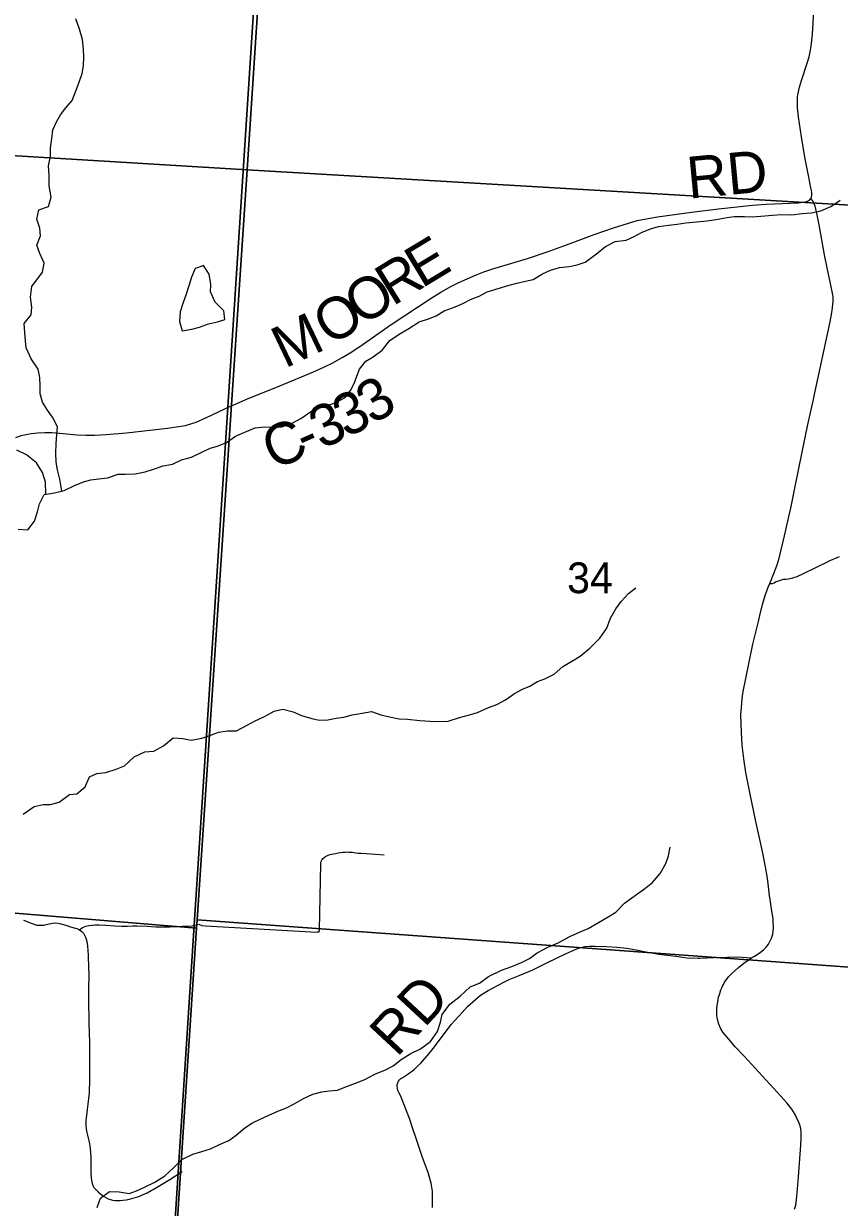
# Model space of a CAD drawing. Extents: x 0 to 34, y 0 to 22.
# Drawn here: x 3.074 to 4.184, y 15.5 to 17.112 of the extents above; entities that cross this region are included whole.
import ezdxf

# ---------------------------------------------------------------- set-up
doc = ezdxf.new("R2010")
doc.units = 0
for name, color, linetype in [('GM_X_Corporation', 7, 'Continuous'), ('GM_X_County_Road', 7, 'Continuous'), ('GM_X_County_Road_Text', 7, 'Continuous'), ('GM_X_Major_River', 7, 'Continuous'), ('GM_X_Minor_Lake', 7, 'Continuous'), ('GM_X_Minor_River', 7, 'Continuous'), ('GM_X_Section_Text', 7, 'Continuous'), ('GM_X_Township_Road', 7, 'Continuous'), ('GM_X_Township_Road_Text', 7, 'Continuous'), ('GM_X_Township_Text', 7, 'Continuous')]:
    doc.layers.add(name, color=color, linetype=linetype)

msp = doc.modelspace()

# ---------------------------------------------------------------- linework, layer by layer
at = {"layer": 'GM_X_Corporation'}
for points in [[(2.1, 19.0816), (2.1, 14.1), (3.1902, 14.1), (3.1919, 14.1255), (3.2339, 14.7735), (3.2844, 15.554), (3.3059, 15.8844), (3.3516, 16.5898), (3.3951, 17.2616), (3.507, 18.9883), (2.9513, 19.0267), (2.509, 19.0572), (2.4972, 19.0545), (2.4649, 19.0567)], [(2.436, 18.0137), (3.4457, 17.9455), (3.3779, 16.9127), (2.3682, 16.9741)], [(3.4457, 17.9455), (4.4596, 17.8697), (4.3853, 16.8539), (3.3779, 16.9127)], [(3.3779, 16.9127), (3.31, 15.8916), (3.3089, 15.8803), (2.2939, 15.964), (2.3682, 16.9741)], [(4.3853, 16.8539), (4.3528, 16.4147), (4.3239, 16.0112), (4.31, 15.819), (3.31, 15.8916), (3.3779, 16.9127)], [(2.2939, 15.964), (3.3089, 15.8803), (3.2437, 14.8797), (2.2272, 14.9411)], [(3.3089, 15.8803), (3.31, 15.8916), (4.31, 15.819), (4.245, 14.8084), (3.2437, 14.8797)]]:
    msp.add_lwpolyline(points, close=True, dxfattribs=at)
at = {"layer": 'GM_X_County_Road'}
for points in [[(3.363, 16.5943), (3.3763, 16.6), (3.4224, 16.6185), (3.4683, 16.6376), (3.4824, 16.644), (3.4935, 16.6496), (3.507, 16.6571), (3.5202, 16.6651), (3.5358, 16.6753), (3.5739, 16.7021), (3.6282, 16.7381), (3.6414, 16.7462), (3.655, 16.7538), (3.6661, 16.7594), (3.6887, 16.7695), (3.7002, 16.7741), (3.7121, 16.778), (3.7596, 16.7922), (3.7891, 16.8021), (3.8212, 16.8137), (3.8502, 16.8246), (3.8765, 16.8338), (3.897, 16.8404), (3.909, 16.8437), (3.9212, 16.8463), (3.9366, 16.8488), (3.9827, 16.8551), (4.0197, 16.8597), (4.066, 16.8646), (4.0846, 16.866), (4.1279, 16.8681), (4.137, 16.8692), (4.1407, 16.8702), (4.1432, 16.8715), (4.1453, 16.8737), (4.1462, 16.8758), (4.1467, 16.8788), (4.1465, 16.8818), (4.1461, 16.8848), (4.1454, 16.8883), (4.1424, 16.9029), (4.1371, 16.9303), (4.1325, 16.9577), (4.1284, 16.985), (4.1272, 16.9974), (4.1269, 17.0064), (4.1272, 17.0122), (4.1275, 17.015), (4.1298, 17.0255), (4.1324, 17.0344), (4.1404, 17.058), (4.1429, 17.0669), (4.1449, 17.0759), (4.1463, 17.0851), (4.1474, 17.0974), (4.1516, 17.1686)], [(3.0632, 16.5485), (3.0704, 16.5509), (3.077, 16.5524), (3.0838, 16.5537), (3.0931, 16.5548), (3.1025, 16.5553), (3.1119, 16.5551), (3.1274, 16.5537), (3.1459, 16.552), (3.1583, 16.5514), (3.1706, 16.5515), (3.186, 16.5523), (3.2138, 16.5548), (3.2694, 16.5609), (3.2847, 16.5631), (3.2938, 16.5648), (3.3027, 16.5672), (3.3085, 16.5693), (3.3226, 16.5756), (3.3563, 16.5915), (3.3576, 16.592), (3.363, 16.5943)]]:
    msp.add_lwpolyline(points, dxfattribs=at)
at = {"layer": 'GM_X_Major_River'}
for points in [[(3.8273, 16.7837), (3.8379, 16.7872), (3.8534, 16.7986), (3.8658, 16.8085), (3.879, 16.8154), (3.8938, 16.817), (3.9048, 16.822), (3.9146, 16.8273), (3.9271, 16.8323), (3.9376, 16.8357), (3.9513, 16.8377), (3.9634, 16.8389), (3.9751, 16.8405), (3.9895, 16.842), (4.0035, 16.8432), (4.0163, 16.8452), (4.0311, 16.8479), (4.0409, 16.8491), (4.0549, 16.8492), (4.0655, 16.8488), (4.0772, 16.8496), (4.0931, 16.8512), (4.1052, 16.852), (4.1192, 16.8517), (4.1332, 16.8533), (4.1461, 16.8545), (4.1586, 16.8568), (4.1722, 16.8629), (4.185, 16.8717)], [(3.0663, 16.4233), (3.0792, 16.4226), (3.0886, 16.4344), (3.0924, 16.4469), (3.0953, 16.4579), (3.1017, 16.4708), (3.1157, 16.4728), (3.129, 16.4763), (3.1429, 16.4831), (3.155, 16.4878), (3.1652, 16.4908), (3.1758, 16.492), (3.1876, 16.4932), (3.2023, 16.4982), (3.2122, 16.4982), (3.2254, 16.4987), (3.239, 16.5014), (3.2504, 16.5052), (3.2636, 16.5098), (3.2761, 16.5122), (3.2885, 16.5179), (3.3021, 16.5214), (3.3161, 16.5283), (3.3275, 16.534), (3.3377, 16.5363), (3.3498, 16.5417), (3.3622, 16.5501), (3.3747, 16.5558), (3.3887, 16.5616), (3.4019, 16.5628), (3.4125, 16.5624), (3.425, 16.5629), (3.4382, 16.5675), (3.4511, 16.574), (3.4643, 16.5831), (3.4749, 16.5892), (3.4851, 16.5916), (3.4976, 16.5954), (3.5115, 16.603), (3.5187, 16.6125), (3.5236, 16.622), (3.527, 16.6319), (3.5307, 16.6414), (3.5394, 16.6524), (3.5492, 16.6582), (3.5616, 16.6673), (3.5722, 16.6802), (3.585, 16.689), (3.5979, 16.6967), (3.6119, 16.7058), (3.6247, 16.71), (3.6353, 16.7139), (3.6462, 16.7207), (3.661, 16.7265), (3.6716, 16.7307), (3.6821, 16.7361), (3.6935, 16.741), (3.7044, 16.7468), (3.7196, 16.7514), (3.7347, 16.7556), (3.7449, 16.7583), (3.757, 16.7614), (3.7672, 16.7637), (3.78, 16.7714), (3.7906, 16.776), (3.8031, 16.7798), (3.816, 16.7814), (3.8273, 16.7837)]]:
    msp.add_lwpolyline(points, dxfattribs=at)
at = {"layer": 'GM_X_Minor_Lake'}
for p, q in [((3.3186, 16.7826), (3.3103, 16.7794)), ((3.3263, 16.7709), (3.3186, 16.7826)), ((3.302, 16.7666), (3.2991, 16.7563)), ((3.3073, 16.7783), (3.302, 16.7666)), ((3.3103, 16.7794), (3.3073, 16.7783)), ((3.3286, 16.7565), (3.3263, 16.7709)), ((3.2991, 16.7563), (3.2946, 16.7423)), ((3.3282, 16.7466), (3.3286, 16.7565)), ((3.2908, 16.7324), (3.2867, 16.7195)), ((3.2946, 16.7423), (3.2908, 16.7324)), ((3.3343, 16.7326), (3.3282, 16.7466)), ((3.3461, 16.7209), (3.3343, 16.7326)), ((3.2867, 16.7195), (3.286, 16.7062)), ((3.3473, 16.7088), (3.3461, 16.7209)), ((3.286, 16.7062), (3.2894, 16.6938)), ((3.3129, 16.6988), (3.3254, 16.703)), ((3.3254, 16.703), (3.3375, 16.7057)), ((3.3375, 16.7057), (3.3473, 16.7088)), ((3.2894, 16.6938), (3.3027, 16.6957)), ((3.3027, 16.6957), (3.3129, 16.6988))]:
    msp.add_line(p, q, dxfattribs=at)
at = {"layer": 'GM_X_Minor_River'}
for p, q in [((3.1499, 17.1043), (3.1449, 17.1183)), ((3.1537, 17.0903), (3.1499, 17.1043)), ((3.1549, 17.0774), (3.1537, 17.0903)), ((3.1557, 17.0665), (3.1549, 17.0774)), ((3.1553, 17.0547), (3.1557, 17.0665)), ((3.1497, 17.0335), (3.1531, 17.0441)), ((3.1531, 17.0441), (3.1553, 17.0547)), ((3.1452, 17.0213), (3.1497, 17.0335)), ((3.1313, 16.9974), (3.1396, 17.0073)), ((3.1396, 17.0073), (3.1452, 17.0213)), ((3.1238, 16.9879), (3.1313, 16.9974)), ((3.1136, 16.9674), (3.1185, 16.978)), ((3.1185, 16.978), (3.1238, 16.9879)), ((3.1121, 16.9556), (3.1136, 16.9674)), ((3.11, 16.9313), (3.1103, 16.9427)), ((3.1103, 16.9427), (3.1121, 16.9556)), ((3.1077, 16.9181), (3.11, 16.9313)), ((3.1082, 16.9052), (3.1077, 16.9181)), ((3.1082, 16.8912), (3.1082, 16.9052)), ((3.1113, 16.8756), (3.1082, 16.8912)), ((3.0943, 16.8585), (3.1076, 16.8627)), ((3.1076, 16.8627), (3.1113, 16.8756)), ((3.0917, 16.8456), (3.0943, 16.8585)), ((3.0955, 16.8335), (3.0917, 16.8456)), ((3.0967, 16.8229), (3.0955, 16.8335)), ((3.0915, 16.8104), (3.0967, 16.8229)), ((3.0957, 16.799), (3.0915, 16.8104)), ((3.1014, 16.7858), (3.0957, 16.799)), ((3.0992, 16.7736), (3.1014, 16.7858)), ((3.0848, 16.7539), (3.0992, 16.7736)), ((3.083, 16.7394), (3.0848, 16.7539)), ((3.0846, 16.7258), (3.083, 16.7394)), ((3.0838, 16.7152), (3.0846, 16.7258)), ((3.0744, 16.7038), (3.0838, 16.7152)), ((3.0752, 16.6913), (3.0744, 16.7038)), ((3.0764, 16.6799), (3.0752, 16.6913)), ((3.0772, 16.6704), (3.0764, 16.6799)), ((3.0841, 16.6553), (3.0772, 16.6704)), ((3.0936, 16.6413), (3.0841, 16.6553)), ((3.0955, 16.63), (3.0936, 16.6413)), ((3.0963, 16.6186), (3.0955, 16.63)), ((3.0963, 16.6076), (3.0963, 16.6186)), ((3.0994, 16.5966), (3.0963, 16.6076)), ((3.1059, 16.5857), (3.0994, 16.5966)), ((3.1131, 16.5759), (3.1059, 16.5857)), ((3.1196, 16.563), (3.1131, 16.5759)), ((3.1189, 16.5528), (3.1196, 16.563)), ((3.1174, 16.527), (3.1178, 16.5399)), ((3.1178, 16.5399), (3.1189, 16.5528)), ((3.0777, 16.5249), (3.0644, 16.5309)), ((3.091, 16.5136), (3.0777, 16.5249)), ((3.1179, 16.5149), (3.1174, 16.527)), ((3.0994, 16.5008), (3.091, 16.5136)), ((3.1198, 16.5043), (3.1179, 16.5149)), ((3.1036, 16.4875), (3.0994, 16.5008)), ((3.1229, 16.4914), (3.1198, 16.5043)), ((3.1255, 16.4754), (3.1229, 16.4914)), ((3.1039, 16.4711), (3.1036, 16.4875)), ((3.8872, 16.325), (3.897, 16.3361)), ((3.897, 16.3361), (3.9068, 16.3437)), ((3.8725, 16.3022), (3.8797, 16.3148)), ((3.8797, 16.3148), (3.8872, 16.325)), ((3.8673, 16.2886), (3.8725, 16.3022)), ((3.8578, 16.2749), (3.8673, 16.2886)), ((3.8443, 16.2612), (3.8578, 16.2749)), ((3.8209, 16.244), (3.8311, 16.2505)), ((3.8311, 16.2505), (3.8443, 16.2612)), ((3.796, 16.2261), (3.8076, 16.2364)), ((3.8076, 16.2364), (3.8209, 16.244)), ((3.7733, 16.2161), (3.7831, 16.2196)), ((3.7831, 16.2196), (3.796, 16.2261)), ((3.7419, 16.1997), (3.7525, 16.2058)), ((3.7525, 16.2058), (3.7627, 16.2097)), ((3.7627, 16.2097), (3.7733, 16.2161)), ((3.7064, 16.1806), (3.7178, 16.1848)), ((3.7178, 16.1848), (3.7295, 16.1909)), ((3.7295, 16.1909), (3.7419, 16.1997)), ((3.3878, 16.1621), (3.4014, 16.1682)), ((3.4014, 16.1682), (3.4146, 16.1755)), ((3.4146, 16.1755), (3.4264, 16.1782)), ((3.4264, 16.1782), (3.4407, 16.1745)), ((3.4407, 16.1745), (3.4517, 16.1696)), ((3.4517, 16.1696), (3.4658, 16.1655)), ((3.5093, 16.1676), (3.521, 16.1707)), ((3.521, 16.1707), (3.5346, 16.173)), ((3.5346, 16.173), (3.5471, 16.175)), ((3.5471, 16.175), (3.56, 16.1705)), ((3.56, 16.1705), (3.5717, 16.1679)), ((3.6671, 16.1668), (3.6807, 16.1706)), ((3.6807, 16.1706), (3.6913, 16.1737)), ((3.6913, 16.1737), (3.7064, 16.1806)), ((3.3632, 16.1487), (3.378, 16.1564)), ((3.378, 16.1564), (3.3878, 16.1621)), ((3.4658, 16.1655), (3.476, 16.1633)), ((3.476, 16.1633), (3.4877, 16.1637)), ((3.4877, 16.1637), (3.4991, 16.166)), ((3.4991, 16.166), (3.5093, 16.1676)), ((3.5717, 16.1679), (3.5846, 16.1653)), ((3.5846, 16.1653), (3.596, 16.1646)), ((3.596, 16.1646), (3.613, 16.1628)), ((3.613, 16.1628), (3.6266, 16.1621)), ((3.6266, 16.1621), (3.6395, 16.1614)), ((3.6395, 16.1614), (3.6516, 16.1622)), ((3.6516, 16.1622), (3.6671, 16.1668)), ((3.2642, 16.1286), (3.277, 16.1393)), ((3.277, 16.1393), (3.2902, 16.1382)), ((3.2902, 16.1382), (3.3016, 16.136)), ((3.3016, 16.136), (3.3164, 16.1387)), ((3.3164, 16.1387), (3.3273, 16.1425)), ((3.3273, 16.1425), (3.339, 16.1471)), ((3.339, 16.1471), (3.3511, 16.1487)), ((3.3511, 16.1487), (3.3632, 16.1487)), ((3.2241, 16.1133), (3.2385, 16.1201)), ((3.2385, 16.1201), (3.2509, 16.1213)), ((3.2509, 16.1213), (3.2642, 16.1286)), ((3.2109, 16.1011), (3.2241, 16.1133)), ((3.1633, 16.0861), (3.1731, 16.0907)), ((3.1731, 16.0907), (3.1856, 16.0922)), ((3.1856, 16.0922), (3.1996, 16.0965)), ((3.1996, 16.0965), (3.2109, 16.1011)), ((3.1459, 16.0629), (3.1572, 16.0728)), ((3.1572, 16.0728), (3.1633, 16.0861)), ((3.1221, 16.0518), (3.1361, 16.0621)), ((3.1361, 16.0621), (3.1459, 16.0629)), ((3.073, 16.0353), (3.0881, 16.0456)), ((3.0881, 16.0456), (3.1002, 16.0483)), ((3.1002, 16.0483), (3.11, 16.0483)), ((3.11, 16.0483), (3.1221, 16.0518))]:
    msp.add_line(p, q, dxfattribs=at)
for points in [[(3.9173, 15.9329), (3.9294, 15.9417), (3.9403, 15.9547), (3.9479, 15.9683), (3.9516, 15.9786), (3.9538, 15.9903)], [(3.1736, 15.4998), (3.1781, 15.5124), (3.1906, 15.5215), (3.2035, 15.5208), (3.2175, 15.5186), (3.2273, 15.5224), (3.2383, 15.5274), (3.2522, 15.5343), (3.2658, 15.5427), (3.2775, 15.5537), (3.2892, 15.5652), (3.304, 15.5721), (3.3161, 15.5759), (3.3278, 15.5794), (3.3402, 15.5855), (3.3531, 15.5908), (3.3629, 15.5981), (3.3746, 15.6084), (3.3852, 15.6149), (3.3958, 15.6202), (3.4063, 15.6252), (3.4196, 15.6309), (3.4313, 15.6352), (3.4419, 15.6409), (3.4547, 15.6482), (3.4672, 15.6539), (3.4796, 15.657), (3.4895, 15.6585), (3.5008, 15.6597), (3.5107, 15.6636), (3.5254, 15.6689), (3.5383, 15.6739), (3.5519, 15.6812), (3.5662, 15.6873), (3.5768, 15.6927), (3.5874, 15.7014), (3.5998, 15.7091), (3.6138, 15.7159), (3.6274, 15.7259), (3.6372, 15.7392), (3.6413, 15.7521), (3.6435, 15.7627), (3.6537, 15.7768), (3.668, 15.7874), (3.6816, 15.8), (3.6941, 15.805), (3.7062, 15.8141), (3.7239, 15.8229), (3.7383, 15.8279), (3.7512, 15.8333), (3.7621, 15.839), (3.7727, 15.8463), (3.787, 15.8543), (3.8014, 15.86), (3.8173, 15.8688), (3.8301, 15.8746), (3.8422, 15.8796), (3.8562, 15.888), (3.8694, 15.8956), (3.8796, 15.9021), (3.8917, 15.9143), (3.9049, 15.9238), (3.9173, 15.9329)]]:
    msp.add_lwpolyline(points, dxfattribs=at)
at = {"layer": 'GM_X_Township_Road'}
for points in [[(4.0644, 15.8395), (4.0687, 15.8421), (4.076, 15.847), (4.0812, 15.8512), (4.0846, 15.8544), (4.0875, 15.8584), (4.0895, 15.8621), (4.0917, 15.8665), (4.0933, 15.872), (4.094, 15.8759), (4.0944, 15.8803), (4.0944, 15.8833), (4.0941, 15.8874), (4.0937, 15.8932), (4.0922, 15.9034), (4.0914, 15.9094), (4.0901, 15.9159), (4.0896, 15.9197), (4.089, 15.9243), (4.0882, 15.9328), (4.0863, 15.9481), (4.0837, 15.9635), (4.0796, 15.9845), (4.0704, 16.0254), (4.0621, 16.0649), (4.0567, 16.0923), (4.0544, 16.1077), (4.0519, 16.1292), (4.0506, 16.1464), (4.0501, 16.1712), (4.0506, 16.1805), (4.0517, 16.1929), (4.0531, 16.2022), (4.0606, 16.24), (4.0662, 16.267), (4.0739, 16.2979), (4.0757, 16.3058), (4.0796, 16.3209), (4.0832, 16.333), (4.0871, 16.3444), (4.0893, 16.3497), (4.0948, 16.3629), (4.0995, 16.3751), (4.1021, 16.384), (4.1095, 16.4142), (4.1163, 16.4445), (4.1179, 16.4523), (4.1223, 16.4749), (4.1294, 16.5084), (4.1413, 16.5662), (4.1487, 16.5999), (4.1493, 16.6026), (4.1715, 16.7059), (4.1741, 16.7212), (4.1756, 16.7336), (4.1757, 16.7366), (4.1755, 16.7398), (4.1751, 16.7428), (4.172, 16.758), (4.1672, 16.7792), (4.1637, 16.7973), (4.1566, 16.8381), (4.1532, 16.854), (4.1509, 16.8633), (4.1492, 16.868), (4.1473, 16.8713), (4.1453, 16.8737)], [(4.0893, 16.3497), (4.0908, 16.3494), (4.0932, 16.3496), (4.0953, 16.3504), (4.0973, 16.3517), (4.0998, 16.3528), (4.1082, 16.3553), (4.1118, 16.3553), (4.1148, 16.3557), (4.1209, 16.3572), (4.1267, 16.3592), (4.1353, 16.363), (4.1686, 16.3796), (4.1692, 16.3798), (4.1844, 16.3864)], [(3.2149, 15.8826), (3.2225, 15.8831), (3.2284, 15.8831), (3.2419, 15.8826), (3.2535, 15.882), (3.2604, 15.8818), (3.2672, 15.8819), (3.2728, 15.882), (3.278, 15.8823), (3.2838, 15.8825), (3.2898, 15.8826), (3.2985, 15.883), (3.3029, 15.8834), (3.3056, 15.8837), (3.3089, 15.8845), (3.3119, 15.8856), (3.316, 15.8839), (3.321, 15.8834), (3.4726, 15.8747), (3.4743, 15.8749), (3.4755, 15.8753), (3.4762, 15.8764), (3.4765, 15.8777), (3.4781, 15.9674), (3.4783, 15.9692), (3.4787, 15.9708), (3.4799, 15.9738), (3.4811, 15.975), (3.4823, 15.976), (3.4834, 15.9768), (3.4847, 15.9777), (3.4864, 15.9785), (3.4883, 15.9794), (3.4906, 15.9802), (3.4929, 15.9808), (3.4955, 15.9814), (3.498, 15.9819), (3.502, 15.9826), (3.5051, 15.9831), (3.508, 15.9835), (3.5108, 15.9838), (3.5135, 15.9839), (3.5162, 15.9838), (3.5208, 15.9834), (3.5237, 15.983), (3.526, 15.9828), (3.5288, 15.9824), (3.5325, 15.9821), (3.54, 15.9817), (3.5643, 15.9801)], [(3.0736, 15.8909), (3.076, 15.8899), (3.0802, 15.8881), (3.0914, 15.8842), (3.0952, 15.884), (3.0983, 15.8841), (3.1013, 15.8843), (3.1044, 15.8851), (3.1086, 15.8862), (3.1131, 15.8871), (3.1166, 15.8873), (3.1205, 15.8869), (3.1241, 15.8861), (3.1311, 15.8841), (3.1376, 15.882), (3.1425, 15.8806), (3.1459, 15.8797), (3.1495, 15.8778), (3.1536, 15.8809), (3.156, 15.882), (3.1584, 15.8828), (3.1623, 15.8837), (3.1665, 15.8842), (3.1673, 15.8843)], [(3.1673, 15.8843), (3.1704, 15.8846), (3.1761, 15.8846), (3.1856, 15.8841), (3.1976, 15.8832), (3.207, 15.8826), (3.2149, 15.8826)], [(3.1495, 15.8778), (3.1531, 15.8753), (3.1549, 15.8733), (3.1566, 15.8707), (3.1579, 15.8679), (3.1589, 15.865), (3.1597, 15.862), (3.1607, 15.8559), (3.1614, 15.8435), (3.1617, 15.8404), (3.1622, 15.8158), (3.162, 15.7979), (3.1621, 15.7915), (3.1621, 15.7895)], [(3.6301, 15.4995), (3.6304, 15.511), (3.6302, 15.5218), (3.6286, 15.5328), (3.6257, 15.5425), (3.6241, 15.5472), (3.6208, 15.5571), (3.6168, 15.568), (3.6119, 15.5813), (3.607, 15.5965), (3.6045, 15.6041), (3.5988, 15.621), (3.5865, 15.6523), (3.5843, 15.6563), (3.5832, 15.6591), (3.5824, 15.662), (3.582, 15.6651), (3.5821, 15.667), (3.5828, 15.6696), (3.5837, 15.6716), (3.5853, 15.6736), (3.5873, 15.6753), (3.5897, 15.6769), (3.5925, 15.6787), (3.5951, 15.6804), (3.5987, 15.6831), (3.6029, 15.686), (3.6055, 15.6881), (3.6102, 15.6924), (3.6141, 15.6964), (3.6255, 15.7092), (3.6327, 15.7183), (3.6555, 15.749), (3.6704, 15.7654), (3.678, 15.7733), (3.6885, 15.7828), (3.6956, 15.7887), (3.7061, 15.7953), (3.7194, 15.8027), (3.7284, 15.8071), (3.7346, 15.8101), (3.748, 15.8155), (3.7666, 15.8234), (3.7859, 15.8331), (3.8113, 15.8451), (3.8196, 15.8489), (3.8266, 15.852), (3.8275, 15.8523)], [(3.8275, 15.8523), (3.8319, 15.8539), (3.8376, 15.855), (3.8438, 15.8557), (3.8511, 15.8558), (3.8672, 15.8553), (3.881, 15.8543), (3.8945, 15.853), (3.9076, 15.8508), (3.9207, 15.8479), (3.9381, 15.8446), (3.9612, 15.8418), (3.977, 15.8397), (3.9918, 15.8393), (3.9939, 15.8392), (4.0141, 15.8402), (4.0317, 15.8408), (4.046, 15.841), (4.0582, 15.84), (4.0644, 15.8395)], [(4.1231, 15.4973), (4.1246, 15.503), (4.1258, 15.5107), (4.1268, 15.5198), (4.1282, 15.5415), (4.1305, 15.5724), (4.1315, 15.5847), (4.1322, 15.594), (4.1321, 15.5972), (4.132, 15.6022), (4.1314, 15.6068), (4.1307, 15.6107), (4.1289, 15.6156), (4.1263, 15.6212), (4.1238, 15.6265), (4.1193, 15.6337), (4.1126, 15.6421), (4.1044, 15.6515), (4.0546, 15.7056), (4.042, 15.7185), (4.0311, 15.7315), (4.0253, 15.7383), (4.0223, 15.7438), (4.0198, 15.7495), (4.019, 15.7525), (4.0177, 15.7586), (4.0174, 15.761), (4.0173, 15.7642), (4.0172, 15.7675), (4.0173, 15.7709), (4.0177, 15.775), (4.0185, 15.78), (4.0197, 15.7861), (4.0211, 15.791), (4.0228, 15.7959), (4.0239, 15.7989), (4.025, 15.8012), (4.0261, 15.8034), (4.0276, 15.8064), (4.0307, 15.8107), (4.0332, 15.8139), (4.0375, 15.8183), (4.0467, 15.8266), (4.054, 15.8324), (4.0644, 15.8395)], [(3.1621, 15.7895), (3.1621, 15.7825), (3.1624, 15.7517), (3.1631, 15.7239), (3.1634, 15.7115), (3.1633, 15.6865), (3.1631, 15.6715), (3.1629, 15.6588), (3.1627, 15.6557), (3.1608, 15.6403), (3.1599, 15.633), (3.159, 15.6252), (3.1584, 15.6185), (3.1584, 15.6151), (3.1584, 15.6115), (3.1588, 15.6077), (3.1594, 15.6036), (3.1606, 15.5983), (3.1628, 15.5888), (3.1633, 15.5866), (3.1636, 15.5836), (3.164, 15.5798), (3.1645, 15.5745), (3.1649, 15.5682), (3.1649, 15.5632), (3.165, 15.5543), (3.1653, 15.5463), (3.1656, 15.5405), (3.1661, 15.5363), (3.1668, 15.5325), (3.1679, 15.5297), (3.1694, 15.5271), (3.1713, 15.5245), (3.1749, 15.5209), (3.1785, 15.518), (3.1825, 15.5151), (3.1856, 15.5132), (3.1886, 15.5117), (3.1917, 15.5105), (3.1946, 15.5098), (3.1981, 15.5093), (3.2018, 15.5092), (3.2051, 15.5092), (3.2088, 15.5097), (3.2132, 15.5103), (3.2179, 15.5112), (3.2239, 15.5127), (3.2304, 15.5148), (3.2356, 15.5169), (3.2416, 15.5196), (3.2473, 15.5227), (3.2498, 15.5242), (3.2726, 15.5379), (3.2894, 15.5487)]]:
    msp.add_lwpolyline(points, dxfattribs=at)
at = {"layer": 'GM_X_Township_Text'}
msp.add_lwpolyline([(8.9, 18.631), (7.8353, 18.6952), (7.8088, 18.6965), (7.389, 18.725), (7.0845, 18.7457), (7.0714, 18.7466), (7.0255, 18.7497), (6.895, 18.7585), (6.4706, 18.7873), (5.6003, 18.8464), (4.4362, 18.9253), (4.421, 18.9263), (4.2931, 18.935), (3.507, 18.9883), (3.3951, 17.2616), (3.3516, 16.5898), (3.3059, 15.8844), (3.2844, 15.554), (3.2339, 14.7735), (3.1919, 14.1255), (3.1902, 14.1)], dxfattribs=at)

# ---------------------------------------------------------------- texts
at = {"layer": 'GM_X_County_Road_Text'}
for s, height, rotation, p in [('RD', 0.05682, 5.4161, (3.9792, 16.8735)), ('E', 0.0568, 31.0813, (3.6155, 16.7509)), ('R', 0.0568, 31.7596, (3.576, 16.7264)), ('O', 0.0568, 33.217, (3.5345, 16.6992)), ('O', 0.0568, 32.3234, (3.4914, 16.672)), ('M', 0.0568, 25.5056, (3.4293, 16.6419)), ('3', 0.0568, 31.0928, (3.5487, 16.5653)), ('3', 0.0568, 26.2923, (3.5127, 16.5473)), ('3', 0.0568, 24.5549, (3.4792, 16.5319)), ('C', 0.0568, 23.6942, (3.4143, 16.5033)), ('-', 0.0568, 23.8897, (3.4572, 16.5222))]:
    msp.add_text(s, height=height, rotation=rotation, dxfattribs=at).set_placement(p)
at = {"layer": 'GM_X_Section_Text'}
msp.add_text('34', height=0.04186, rotation=0, dxfattribs=at).set_placement((3.8134, 16.3363))
at = {"layer": 'GM_X_Township_Road_Text'}
msp.add_text('RD', height=0.05682, rotation=47.0941, dxfattribs=at).set_placement((3.5816, 15.7031))

doc.saveas('drawing.dxf')
